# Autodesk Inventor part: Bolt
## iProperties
Shininess: 77.0
Length Units: 11269
Angle Units: 11279
Time Units: 11290
Mass Units: 11283
Length Display Precision: 3
Angle Display Precision: 2
Created: 2002-02
Part Number: Bolt
Document SubType Name: Modeling
Designer: ***
Density: 0.0
Volumn: 0.0
Area: 0.0
PropertySet Name: Model Information
Control State: 0
Master: False
Checked Out: False
Author: ***
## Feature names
1. Extrusion1
2. Fillet1
3. Extrusion2
4. Extrusion3
